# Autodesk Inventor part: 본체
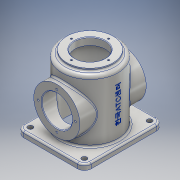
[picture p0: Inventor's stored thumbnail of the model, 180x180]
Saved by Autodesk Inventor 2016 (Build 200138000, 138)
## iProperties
Created: 2021-02
Part Number: 본체
Material: 알루미늄 6061
Document SubType Name: Modeling
Designer: user
Density: 2.7 g/cm^3
Appearance: 알루미늄 - 평지
Mass: 1236.22 g
Surface Area: 1064.5 cm^2
Volume: 457.859 cm^3
Author: user
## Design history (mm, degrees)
sketch "스케치5"
  geometry: L1 (-60, -70)-(60, -70); L2 (60, -70)-(60, 70); L3 (60, 70)-(-60, 70); L4 (-60, 70)-(-60, -70); L5 (-60, -70)-(60, 70); L6 (60, -70)-(-60, 70); 1 further point
  constraints: 12 end point, 2 midpoint, 2 parallel, 1 horizontal, 1 perpendicular
  dimensions: "d28" = 120 distance of L3.end L2.end; "d29" = 140 distance of L2.end L1.end
extrude "돌출4" new body sketch "스케치5" distance "d30" = 10; taper "d31" = 0 deg
sketch "스케치6"
  geometry: C1 r 50 at (0, 0); 1 further point
  constraints: 1 centre point, 1 coincident
  dimensions: "d32" = 100 diameter of C1
extrude "돌출5" join sketch "스케치6" distance "d33" = 110; taper "d34" = 0 deg
sketch "스케치7"
  geometry: C1 r 41 at (0, 0); 1 further point
  constraints: 1 centre point, 1 coincident
  dimensions: "d35" = 82 diameter of C1
extrude "돌출6" join sketch "스케치7" distance "d36" = 5; taper "d37" = 0 deg
hole "구멍3" diameter "d40" = 54; stored, may be unused: countersink angle "d44" = 90 deg, drill point angle "d46" = 0 deg; dims "d38" = 10, "d39" = 10, "d41" = 6, "d42" = 54, "d43" = 13, "d45" = 13
hole "구멍4" diameter "d49" = 84; stored, may be unused: countersink angle "d53" = 90 deg, drill point angle "d55" = 0 deg; dims "d47" = 60, "d48" = 70.058, "d50" = 6, "d51" = 54, "d52" = 13, "d54" = 112
node "작업 평면1"
sketch "스케치10"
  geometry: L1 (60, 0)-(-60, 0) reference; C1 r 41 at (0, 60); 1 further point
  constraints: 1 centre point
  dimensions: "d57" = 82 diameter of C1; "d58" = 60 distance of point (0, 0) C1.centre; "d59" = 60 distance from line of L1 C1.centre
extrude "돌출7" join sketch "스케치10" stored distance "d60" = 15; taper "d61" = 0 deg
hole "구멍5" diameter "d64" = 54; stored, may be unused: countersink angle "d68" = 90 deg, drill point angle "d70" = 0 deg; dims "d62" = 10, "d63" = 10, "d65" = 6, "d66" = 54, "d67" = 13, "d69" = 59
sketch "스케치11" dims "d71" = 66
  geometry: C1 r 41 at (0, 0) reference; 3 further points
  constraints: 2 vertical alignment, 1 coincident, 2 other
hole "구멍6" sketch "스케치11" at (0, 33) diameter "d72" = 3.242; stored, may be unused: countersink angle "d76" = 90 deg, drill point angle "d78" = 118 deg; dims "d73" = 8, "d74" = 54, "d75" = 13, "d77" = 10
sketch "스케치12" dims "d82" = 66
  geometry: C1 r 41 at (0, 0) reference; 3 further points
  constraints: 2 vertical alignment, 1 coincident, 2 other
hole "구멍7" sketch "스케치12" at (0, 33) diameter "d83" = 3.242; stored, may be unused: countersink angle "d87" = 90 deg, drill point angle "d89" = 118 deg; dims "d84" = 8, "d85" = 54, "d86" = 13, "d88" = 10
fillet "모깎기1" dims "d93" = 12
chamfer "모따기1" distance "d94" = 1; stored, may be unused: second distance "d95" = 2, angle "d96" = 45 deg
hole "구멍8" diameter "d99" = 9; stored, may be unused: countersink angle "d103" = 90 deg, drill point angle "d105" = 0 deg; dims "d97" = 10, "d98" = 10, "d100" = 8, "d101" = 54, "d102" = 13, "d104" = 10
fillet "모깎기2" dims "d112" = 3
fillet "모깎기3" dims "d113" = 6
fillet "모깎기4" dims "d114" = 3
fillet "모깎기5" dims "d115" = 3
node "작업 평면2"
sketch "스케치13"
  geometry: 1 further point
sketch "스케치14"
  geometry: L1 (-58, 0)-(58, 0) reference; 2 further points
  constraints: 1 other
  dimensions: "d117" = 66 distance from line of L1 point (0, 66); "d118" = 0 horizontal distance of point (0, 0) point (0, 66)
feature "엠보싱1" sketch "스케치14" dims "d41" = 6, "d119" = 0.5, "d120" = 0
fillet "모깎기6" dims "d121" = 3
chamfer "모따기2" distance "d122" = 1; stored, may be unused: second distance "d123" = 2, angle "d124" = 45 deg
node "솔리드2"
pattern_circular "원형 패턴1" dims angle "d80" = 360 deg
pattern_circular "원형 패턴2" dims angle "d91" = 360 deg
pattern_linear "직사각형 패턴1" dims "d108" = 96, "d111" = 116
mirror "대칭2"
mirror "대칭3"
mirror "대칭4"
other parameters: "d56" = -59
